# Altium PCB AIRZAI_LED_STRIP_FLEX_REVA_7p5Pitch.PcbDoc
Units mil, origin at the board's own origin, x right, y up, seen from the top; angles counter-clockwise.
Board outline 6727.47 x 711.99 mil, 2 copper layers (Top Layer, Bottom Layer); 43 components, 44 nets, 218 pads, 46 vias.
Unrouted connection lines stored in the file: 63.
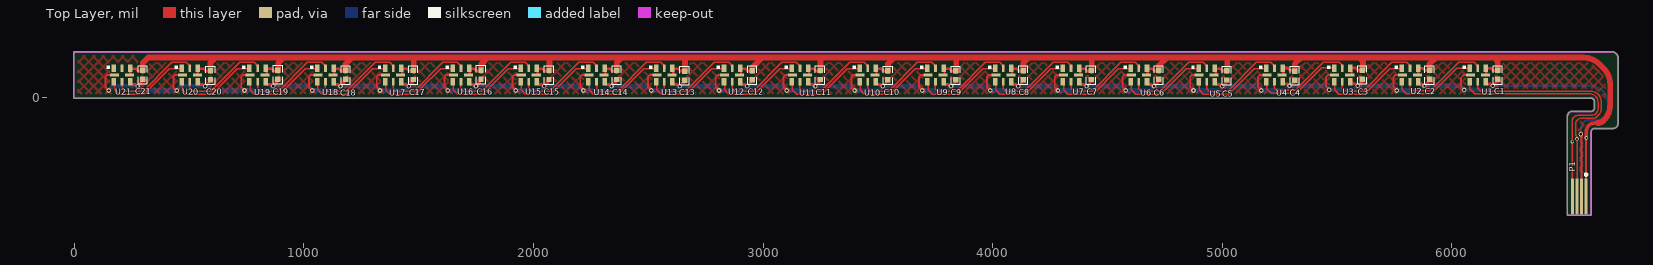
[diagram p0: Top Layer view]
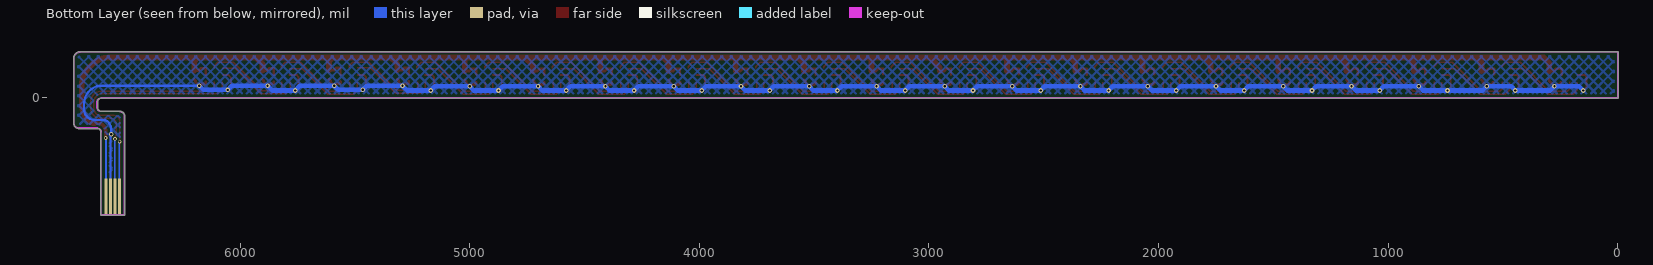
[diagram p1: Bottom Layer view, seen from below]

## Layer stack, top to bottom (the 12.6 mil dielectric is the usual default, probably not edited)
Top Solder: solder mask 0.4, Solder Resist, Dk 3.5
Top Layer: signal copper 1.4
Dielectric 1: dielectric 12.6, FR-4, Dk 4.8
Bottom Layer: signal copper 1.4
Bottom Solder: solder mask 0.4, Solder Resist, Dk 3.5

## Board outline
6503.5,-510.11 ccw(c6506.02,-510.11) 6506.02,-512.63 6604.44,-512.63 ccw(c6604.44,-510.11) 6606.96,-510.11 6606.96,-152 ccw(c6604.44,-152) 6606.95,-151.79 cw(c6622.38,-150.62) 6621.1,-135.2 6702.76,-135.2 ccw(c6702.76,-113) 6724.96,-113 ccw(c6722.44,-113) 6723.97,-111 ccw(c6722.44,-109) 6724.96,-109 6724.96,171.81 ccw(c6697.4,171.81) 6697.4,199.37 0,199.37 ccw(c0,196.85) -2.52,196.85 -2.52,0 ccw(c0,0) 0,-2.52 6604.33,-2.51 ccw(c6604.33,0) 6604.33,-2.51 cw(c6604.33,-19.68) 6621.5,-19.68 6621.5,-43 cw(c6604.33,-43) 6604.33,-60.17 6524.02,-60.17 cw(c6523.67,-80.34) 6524.05,-60.17 6524.02,-60.17 ccw(c6523.67,-80.34) 6503.5,-79.95 ccw(c6506.02,-80) 6503.5,-80
board region "Layer Stack Region 1": 6606.95,-294 6606.96,-510.11 6606.96,-510.61 6606.57,-511.54 6605.87,-512.24 6604.94,-512.63 6604.44,-512.63 6506.02,-512.63 6505.52,-512.63 6504.59,-512.24 6503.88,-511.54 6503.5,-510.61 6503.5,-510.11 6503.5,-294
board region "Layer Stack Region 1": 6368,199.37 6697.4,199.37 6700.12,199.37 6705.44,198.31 6710.45,196.23 6714.97,193.21 6718.8,189.38 6721.82,184.86 6723.9,179.85 6724.96,174.52 6724.96,171.81 6724.96,-109 6724.82,-109.86 6724.57,-110.38 6723.97,-111 6724.57,-111.62 6724.82,-112.14 6724.96,-112.71 6724.96,-117.42 6721.58,-125.58 6715.33,-131.82 6707.17,-135.2 6702.76,-135.2 6621.1,-135.2 6618.13,-135.74 6612.78,-138.48 6608.88,-143.06 6607.01,-148.77 6606.95,-151.79 6606.95,-230 6503.5,-230.01 6503.5,-80 6503.58,-75.95 6506.78,-68.6 6512.55,-63.03 6520.01,-60.1 6524.02,-60.17 6604.33,-60.17 6607.68,-59.84 6613.87,-57.28 6618.61,-52.54 6621.17,-46.35 6621.5,-43 6621.5,-19.69 6621.17,-16.34 6618.61,-10.15 6613.87,-5.41 6607.68,-2.85 6604.33,-2.52 6368,-2.52
board region "Layer Stack Region 1": 6503.5,-294 6503.5,-230.01 6606.95,-230 6606.95,-294
board region "Layer Stack Region 1": 6289,-2.52 0,-2.52 -0.5,-2.52 -1.42,-2.13 -2.13,-1.43 -2.52,-0.5 -2.52,0 -2.52,196.85 -2.52,197.35 -2.13,198.28 -1.42,198.98 -0.5,199.37 0,199.37 6289,199.37
board region "Layer Stack Region 3": 6368,-2.52 6289,-2.52 6289,199.37 6368,199.37

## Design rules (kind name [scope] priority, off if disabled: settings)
Clearance Clearance_polygon_5V [OnLayer('Keep-Out Layer') vs (InNet('+5V') AND InPolygon)] p1: gap=10 ignorepadtopadclearanceinfootprint=FALSE
Clearance Clearance_POLYGON_KEEPOUT [(OnLayer('Keep-Out Layer')) vs (InNet('GND') AND InPolygon)] p2: gap=10 ignorepadtopadclearanceinfootprint=FALSE
Clearance [All] p3: gap=6 ignorepadtopadclearanceinfootprint=FALSE
MinimumSolderMaskSliver [All] p1: minsoldermaskwidth=1
PolygonConnect [All] p1: connectstyle=Direct reliefconductorwidth=10 reliefentries=4 polygonreliefangle="90 Angle" airgapwidth=10
RoomDefinition AIRZAI_LED_STRIP_FLEX_REVA_7p5Pitch [InComponentClass('AIRZAI_LED_STRIP_FLEX_REVA_7p5Pitch')] p1: confinementstyle=ConfineIn formatcopy=TRUE lockcomponents=FALSE outline -3699.89,-5126.44 10960.11,-5126.44 10960.11,4473.56 -3699.89,4473.56
RoutingVias [All] p1: holewidth=28 width=50 viastyle="Through Hole" minholewidth=8 minwidth=16 maxholewidth=28 maxwidth=50
SilkToSilkClearance [All] p1: silktosilkclearance=1
SilkToSolderMaskClearance [IsPad] p1: minsilkscreentomaskgap=2 clearancetoexposedcopper=TRUE
SolderMaskExpansion [All] p1: expansion=4
UnRoutedNet [All] p1: checkbadconnections=TRUE
Width [All] p1: maxlimit=100 minlimit=6 preferedwidth=10
26 further rules are at their usual default settings.

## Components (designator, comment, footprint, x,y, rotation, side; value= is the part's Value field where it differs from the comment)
C1 "0.1µF" 0402CAP 6200.25,98.43 r270 top
C2 "0.1µF" 0402CAP 5903.14,98.43 r270 top
C3 "0.1µF" 0402CAP 5609.7,99.11 r270 top
C4 "0.1µF" 0402CAP 5315.92,95.43 r270 top
C5 "0.1µF" 0402CAP 5020.25,96.11 r270 top
C6 "0.1µF" 0402CAP 4723.87,98.43 r270 top
C7 "0.1µF" 0402CAP 4428.6,98.11 r270 top
C8 "0.1µF" 0402CAP 4133.32,97.46 r270 top
C9 "0.1µF" 0402CAP 3839.05,96.93 r270 top
C10 "0.1µF" 0402CAP 3543.77,97.11 r270 top
C11 "0.1µF" 0402CAP 3248.17,98.11 r270 top
C12 "0.1µF" 0402CAP 2953.22,97.61 r270 top
C13 "0.1µF" 0402CAP 2657.94,95.42 r270 top
C14 "0.1µF" 0402CAP 2362.1,98.11 r270 top
C15 "0.1µF" 0402CAP 2067.39,98.11 r270 top
C16 "0.1µF" 0402CAP 1771.49,99.64 r270 top
C17 "0.1µF" 0402CAP 1476.84,98.11 r270 top
C18 "0.1µF" 0402CAP 1181.57,98.64 r270 top
C19 "0.1µF" 0402CAP 886.73,99.58 r270 top
C20 "0.1µF" 0402CAP 593.02,97.11 r270 top
C21 "0.1µF" 0402CAP 298.06,99.43 r270 top
P1 "Header 4" FFC_4PADS 6555.23,-431.39 r0 top
U1 "APA102-2020-256-8" APA102–2020 6113.25,98.43 r270 top
U2 "APA102-2020-256-8" APA102–2020 5817.98,98.43 r270 top
U3 "APA102-2020-256-8" APA102–2020 5522.7,98.43 r270 top
U4 "APA102-2020-256-8" APA102–2020 5227.43,98.43 r270 top
U5 "APA102-2020-256-8" APA102–2020 4932.25,98.43 r270 top
U6 "APA102-2020-256-8" APA102–2020 4636.87,98.43 r270 top
U7 "APA102-2020-256-8" APA102–2020 4341.6,98.43 r270 top
U8 "APA102-2020-256-8" APA102–2020 4046.32,98.43 r270 top
U9 "APA102-2020-256-8" APA102–2020 3751.05,98.43 r270 top
U10 "APA102-2020-256-8" APA102–2020 3455.77,98.43 r270 top
U11 "APA102-2020-256-8" APA102–2020 3160.5,98.43 r270 top
U12 "APA102-2020-256-8" APA102–2020 2865.22,98.43 r270 top
U13 "APA102-2020-256-8" APA102–2020 2569.94,98.43 r270 top
U14 "APA102-2020-256-8" APA102–2020 2274.67,98.43 r270 top
U15 "APA102-2020-256-8" APA102–2020 1979.39,98.43 r270 top
U16 "APA102-2020-256-8" APA102–2020 1684.12,98.43 r270 top
U17 "APA102-2020-256-8" APA102–2020 1388.84,98.43 r270 top
U18 "APA102-2020-256-8" APA102–2020 1093.57,98.43 r270 top
U19 "APA102-2020-256-8" APA102–2020 798.29,98.43 r270 top
U20 "APA102-2020-256-8" APA102–2020 503.02,98.43 r270 top
U21 "APA102-2020-256-8" APA102–2020 207.74,98.43 r270 top

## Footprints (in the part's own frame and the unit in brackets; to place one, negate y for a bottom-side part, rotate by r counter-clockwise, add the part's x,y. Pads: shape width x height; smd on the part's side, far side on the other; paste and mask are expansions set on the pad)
0402CAP [mm] "Chip Capacitor, Body 1.1x0.5mm, IPC High Density"
  rect 0.6x0.6 smd: 1(-0.5,0) 2(0.5,0)
  silkscreen extent -1.02,-0.51 1.02,0.51, body extent -0.5,-0.3 0.5,0.3, height 0.19
APA102–2020 [mm]
  rect 0.8x0.5 smd: 1(-0.75,0.9) 3(-0.75,-0.9) 4(0.75,-0.9) 6(0.75,0.9)
  rect 0.8x0.3 smd: 2(-0.75,0) 5(0.75,0)
  rect 0.3x1 smd: 7(0,-0.83) 8(0,0.83)
  silkscreen extent -1.02,-1.7 -0.63,-1.32, body extent -1,-1 1,1, height 0.94
FFC_4PADS [mm] "(0.50mm"
  rect 0.3x4 smd: 1(0.75,0) 2(0.25,0) 3(-0.25,0) 4(-0.75,0)
  rect 0.3x4 smd far side: 1(0.75,0) 2(0.25,0) 3(-0.25,0) 4(-0.75,0)
  silkscreen extent 0.64,2.31 0.89,2.56

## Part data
C1 C2 C3 C4 C5 C6 C7 C8 C9 C10 C11 C12 C13 C14 C15 C16 C17 C18 C19 C20 C21: library part C0402-100n, "Capacitor, X7R, ±10%", Case-EIA=0402, Case-Metric=1005, Manufacturer=TDK, Manufacturer Part Number=C1005X7R1C104K, Rated Voltage="16 V", Supplier Part Number 1=445-4952-2-ND, Tolerance=±20%
P1: "Header, 4-Pin"
U1 U2 U3 U4 U5 U6 U7 U8 U9 U10 U11 U12 U13 U14 U15 U16 U17 U18 U19 U20 U21: "DotStar Micro LEDs", Package="SOIC-20 Adafruit Industries"

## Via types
v1: diameter 20, hole 10, Top Layer to Bottom Layer, tented both sides, 43 vias
v2: diameter 16, hole 8, Top Layer to Bottom Layer, tented both sides, 3 vias

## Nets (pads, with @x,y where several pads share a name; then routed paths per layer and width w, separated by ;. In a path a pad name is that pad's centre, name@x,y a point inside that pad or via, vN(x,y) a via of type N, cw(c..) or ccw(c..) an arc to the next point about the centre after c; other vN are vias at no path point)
+5V: C1.1 C2.1 C3.1 C4.1 C5.1 C6.1 C7.1 C8.1 C9.1 C10.1 C11.1 C12.1 C13.1 C14.1 C15.1 C16.1 C17.1 C18.1 C19.1 C20.1 C21.1 P1.1 U1.1 U1.8 U2.1 U2.8 U3.1 U3.8 U4.1 U4.8 U5.1 U5.8 U6.1 U6.8 U7.1 U7.8 U8.1 U8.8 U9.1 U9.8 U10.1 U10.8 U11.1 U11.8 U12.1 U12.8 U13.1 U13.8 U14.1 U14.8 U15.1 U15.8 U16.1 U16.8 U17.1 U17.8 U18.1 U18.8 U19.1 U19.8 U20.1 U20.8 U21.1 U21.8 | length 10913.6
  Top Layer w10: U21.8@242.92,97.69 U21.1@242.92,123.33 ; U20.8@537.92,100 U20.1@537.92,125.64 ; U19.8@837.65,100 U19.1@837.65,125.64 ; U18.8@1131.84,98.42 U18.1@1131.84,125.64 ; U17.8@1428.2,100 U17.1@1428.2,125.64 ; U16.8@1722.3,98.42 U16.1@1722.3,125.64 ; U15.8@2018.75,100 U15.1@2018.75,125.64 ; U14.8@2312.89,98.43 U14.1@2312.89,125.64 ; U13.8@2609.3,100 U13.1@2609.3,125.64 ; U12.8@2903.5,98.43 U12.1@2903.5,125.64 ; U11.8@3199.85,100 U11.1@3199.85,125.64 ; U10.8@3494.05,98.43 U10.1@3494.05,125.64 ; U9.8@3790.4,100 U9.1@3790.4,125.64 ; U8.8@4084.6,98.43 U8.1@4084.6,125.64 ; U7.8@4380.95,100 U7.1@4380.95,125.64 ; U6.8@4675.15,98.43 U6.1@4675.15,125.64 ; U5.8@4971.61,100 U5.1@4971.61,125.64 ; U4.8@5262.95,99.12 5264.8,99.12 5265.7,100.02 U4.1@5265.7,128.64 ; U3.8@5562.06,99.12 5562.96,100.02 U3.1@5562.96,128.64 ; U2.8 5852.5,98.43 5853.41,99.33 U2.1 ; U1.8@6149.61,98.43 6150.52,99.33 U1.1@6150.52,127.95 ; P1.1@6584.76,-399.39 6584.76,-181.5 6584.87,-181.39 6584.87,-177.15 v2(6586.02,-176)
  Top Layer w12: U21.1@247.1,125.65 267.65,125.65 277.49,115.8 C21.1@297.74,115.8 ; U20.1@542.37,125.64 562.92,125.64 572.77,115.8 C20.1@593.01,115.8 ; U19.1@837.65,125.64 858.2,125.64 868.04,115.8 C19.1@888.29,115.8 ; U18.1@1131.84,125.64 1151.49,125.64 1161.33,115.8 C18.1@1181.58,115.8 ; U17.1@1428.2,125.64 1448.75,125.64 1458.59,115.8 C17.1@1478.84,115.8 ; U16.1@1722.3,125.64 1741.95,125.64 1751.79,115.8 C16.1@1772.03,115.8 ; U15.1@2018.75,125.64 2039.3,125.64 2049.14,115.8 C15.1@2069.39,115.8 ; U14.1@2312.89,125.64 2332.54,125.64 2342.38,115.8 C14.1@2362.62,115.8 ; U13.1@2609.3,125.64 2629.85,125.64 2639.69,115.8 C13.1@2659.94,115.8 ; U12.1@2903.5,125.64 2923.14,125.64 2932.99,115.8 C12.1@2953.23,115.8 ; U11.1@3199.85,125.64 3220.4,125.64 3230.25,115.8 C11.1@3250.49,115.8 ; U10.1@3494.05,125.64 3513.7,125.64 3523.54,115.8 C10.1@3543.78,115.8 ; U9.1@3790.4,125.64 3810.95,125.64 3820.8,115.8 C9.1@3841.04,115.8 ; U8.1@4084.6,125.64 4104.25,125.64 4114.09,115.8 C8.1@4134.33,115.8 ; U7.1@4380.95,125.64 4401.51,125.64 4411.35,115.8 C7.1@4431.59,115.8 ; U6.1@4675.15,125.64 4694.8,125.64 4704.64,115.8 C6.1@4724.88,115.8 ; U5.1@4971.61,125.64 4992.16,125.64 5002,115.8 C5.1@5022.25,115.8 ; U4.1@5265.7,128.64 5285.35,128.64 5295.19,118.8 C4.1@5315.43,118.8 ; U3.1@5562.96,128.64 5582.61,128.64 5592.45,118.8 C3.1@5612.69,118.8 ; U2.1 5873.06,127.95 5882.9,118.11 C2.1 ; U1.1@6150.52,127.95 6170.17,127.95 6180.01,118.11 C1.1
  Top Layer w16: v2(6586.02,-176) 6586.02,-146.1 cw(c6620.1,-146.1) 6596,-122 cw(c6622.52,-148.52) 6622.52,-111.01 6635.58,-111.01
  Top Layer w25: C21.1@297.74,115.8 297.74,150 297.81,150 322.02,174.2 617.29,174.2 ; C20.1@593.01,115.8 593.01,150 593.09,150 617.29,174.2 ; C19.1@888.29,115.8 888.29,150 888.36,150 912.56,174.2 ; C18.1@1181.58,115.8 1181.58,144.79 1210.99,174.2 ; 1473.01,174.2 1478.84,168.38 C17.1@1478.84,115.8 ; C16.1@1772.03,115.8 1772.03,145.1 1801.13,174.2 ; 1899.65,174.2 2063.96,174.2 2069.39,168.77 C15.1@2069.39,115.8 ; C14.1@2362.62,115.8 2362.62,152.19 2384.63,174.2 2437.43,174.2 ; 2535.91,174.2 2657.71,174.2 2659.94,171.97 C13.1@2659.94,115.8 ; C12.1@2953.23,115.8 2953.23,129.99 2997.44,174.2 ; 3095.86,174.2 3243.29,174.2 ; C11.1@3250.49,115.8 3250.49,167 3243.29,174.2 ; 3250.49,174.2 3243.29,174.2 ; C10.1@3543.78,115.8 3543.78,146.17 3571.82,174.2 ; C9.1@3841.04,115.8 3841.04,174.2 ; C8.1@4134.33,115.8 4134.33,150.29 4158.24,174.2 ; C7.1@4431.59,115.8 4431.59,168.87 4426.26,174.2 ; C6.1@4724.88,115.8 4724.88,138.99 4760.09,174.2 ; C5.1@5022.25,115.8 5022.25,174.2 ; C4.1@5315.43,118.8 5315.43,145.77 5339.31,169.64 ; 5596.95,174.2 5612.69,158.45 C3.1@5612.69,118.8 ; C2.1 5903.14,146.22 5930.33,173.41 5929.54,174.2 ; C1.1 6200.25,157.76 6183.81,174.2 ; 6635.58,-111.01 ccw(c6635.58,-75.07) 6661,-100.49 ccw(c6590.99,-30.47) 6690,-30.47 6690,56.58 ccw(c6590,56.58) 6660.71,127.29 6643.09,144.91 ccw(c6572.38,74.2) 6572.38,174.2 6183.81,174.2 ; 617.29,174.2 912.56,174.2 ; 912.56,174.2 5022.25,174.2 ; 4426.26,174.2 4344.59,174.2 4426.26,174.2 ; 5022.25,174.2 6183.81,174.2
  Bottom Layer w10: P1.1@6584.76,-399.39 6584.76,-181.5 6584.87,-181.39 6584.87,-177.37 6584.76,-177.26 v2(6586.02,-176)
GND: C1.2 C2.2 C3.2 C4.2 C5.2 C6.2 C7.2 C8.2 C9.2 C10.2 C11.2 C12.2 C13.2 C14.2 C15.2 C16.2 C17.2 C18.2 C19.2 C20.2 C21.2 P1.2 U1.6 U1.7 U2.6 U2.7 U3.6 U3.7 U4.6 U4.7 U5.6 U5.7 U6.6 U6.7 U7.6 U7.7 U8.6 U8.7 U9.6 U9.7 U10.6 U10.7 U11.6 U11.7 U12.6 U12.7 U13.6 U13.7 U14.6 U14.7 U15.6 U15.7 U16.6 U16.7 U17.6 U17.7 U18.6 U18.7 U19.6 U19.7 U20.6 U20.7 U21.6 U21.7 | length 11410.5
  Top Layer w8: v1(150.5,30.69) 136.43,44.76 136.43,90.55 144.31,98.43 U21.7 ; v1(445.78,30.69) 431.7,44.76 431.7,90.55 439.58,98.43 U20.7 ; v1(741.05,30.69) 726.98,44.76 726.98,90.54 734.86,98.43 U19.7 ; v1(1036.32,30.69) 1022.25,44.76 1022.25,90.54 1030.13,98.43 U18.7 ; v1(1331.6,30.69) 1317.53,44.76 1317.53,90.54 1325.41,98.43 U17.7 ; v1(1626.88,30.69) 1612.8,44.76 1612.8,90.54 1620.68,98.43 U16.7 ; v1(1922.15,30.69) 1908.08,44.76 1908.08,90.54 1915.96,98.43 U15.7 ; v1(2217.43,30.69) 2203.35,44.76 2203.35,90.54 2211.24,98.43 U14.7 ; v1(2512.7,30.69) 2498.63,44.76 2498.63,90.54 2506.51,98.43 U13.7 ; v1(2807.98,30.69) 2793.91,44.76 2793.91,90.54 2801.79,98.43 U12.7 ; v1(3103.25,30.69) 3089.18,44.76 3089.18,90.54 3097.06,98.43 U11.7 ; v1(3398.53,30.69) 3384.46,44.76 3384.46,90.54 3392.34,98.43 U10.7 ; v1(3693.8,30.69) 3679.73,44.76 3679.73,90.54 3687.61,98.43 U9.7 ; v1(3989.08,30.69) 3975.01,44.76 3975.01,90.54 3982.89,98.43 U8.7 ; v1(4284.36,30.69) 4270.28,44.76 4270.28,90.54 4278.17,98.43 U7.7 ; v1(4579.63,30.69) 4565.56,44.76 4565.56,90.54 4573.44,98.43 U6.7 ; v1(4875.01,30.69) 4860.94,44.76 4860.94,90.54 4868.82,98.43 U5.7 ; v1(5170.18,30.69) 5156.11,44.76 5156.11,90.54 5163.99,98.43 U4.7 ; v1(5466.46,33.69) 5452.39,47.76 5452.39,89.56 5461.25,98.43 U3.7@5488.02,98.43 ; v1(5760.73,30.69) 5746.66,44.76 5746.66,90.54 5754.54,98.43 U2.7 ; v1(6054.02,33) 6039.94,47.07 6039.94,86.12 6052.25,98.43 U1.7@6076.27,98.43
  Top Layer w10: v1@6563.93,-161.91 v1(6562.02,-160) 6562.02,-170 6565.07,-173.05 P1.2@6565.07,-399.39
  Top Layer w12: U21.6@248,66.59 248,60.68 251.85,56.84 265.02,56.84 273.17,48.69 v1(275.34,48.69) 298.06,71.42 C21.2 ; U20.6@543.28,66.59 543.28,60.68 547.12,56.84 560.3,56.84 568.45,48.69 v1(570.61,48.69) 587.2,65.28 587.2,70.62 C20.2@593.01,76.43 ; U19.6@838.55,66.59 838.55,60.68 842.4,56.84 855.57,56.84 863.72,48.69 v1(865.88,48.69) 882.47,65.28 882.47,70.62 C19.2@888.29,76.43 ; U18.6@1131.84,66.59 1131.84,60.68 1135.69,56.84 1148.86,56.84 1157.01,48.69 v1(1159.17,48.69) 1175.76,65.28 1175.76,70.62 C18.2@1181.58,76.43 ; U17.6@1429.1,66.59 1429.1,60.68 1432.95,56.84 1446.12,56.84 1454.27,48.69 v1(1456.43,48.69) 1473.02,65.28 1473.02,70.62 C17.2@1478.84,76.43 ; U16.6@1722.3,66.59 1722.3,60.68 1726.14,56.84 1739.32,56.84 1747.47,48.69 v1(1749.63,48.69) 1766.22,65.28 1766.22,70.62 C16.2@1772.03,76.43 ; U15.6@2019.65,66.59 2019.65,60.68 2023.5,56.84 2036.67,56.84 2044.82,48.69 v1(2046.99,48.69) 2063.58,65.28 2063.58,70.62 C15.2@2069.39,76.43 ; U14.6@2312.89,66.59 2312.89,60.68 2316.73,56.84 2329.91,56.84 2338.06,48.69 v1(2340.22,48.69) 2356.81,65.28 2356.81,70.62 C14.2@2362.62,76.43 ; U13.6@2610.21,66.59 2610.21,60.68 2614.05,56.84 2627.22,56.84 2635.37,48.69 v1(2637.54,48.69) 2654.13,65.28 2654.13,70.62 C13.2@2659.94,76.43 ; U12.6@2903.5,66.59 2903.5,60.68 2907.34,56.84 2920.51,56.84 2928.66,48.69 v1(2930.83,48.69) 2947.42,65.28 2947.42,70.62 C12.2@2953.23,76.43 ; U11.6@3200.76,66.59 3200.76,60.68 3204.6,56.84 3217.77,56.84 3225.92,48.69 v1(3228.09,48.69) 3244.68,65.28 3244.68,70.62 C11.2@3250.49,76.43 ; U10.6@3494.05,66.59 3494.05,60.68 3497.89,56.84 3511.07,56.84 3519.22,48.69 v1(3521.38,48.69) 3537.97,65.28 3537.97,70.62 C10.2@3543.78,76.43 ; U9.6@3791.31,66.59 3791.31,60.68 3795.15,56.84 3808.32,56.84 3816.47,48.69 v1(3818.64,48.69) 3835.23,65.28 3835.23,70.62 C9.2@3841.04,76.43 ; U8.6@4084.6,66.59 4084.6,60.68 4088.44,56.84 4101.62,56.84 4109.77,48.69 v1(4111.93,48.69) 4128.52,65.28 4128.52,70.62 C8.2@4134.33,76.43 ; U7.6@4381.86,66.59 4381.86,60.68 4385.7,56.84 4398.88,56.84 4407.03,48.69 v1(4409.19,48.69) 4425.78,65.28 4425.78,70.62 C7.2@4431.59,76.43 ; U6.6@4675.15,66.59 4675.15,60.68 4678.99,56.84 4692.17,56.84 4700.32,48.69 v1(4702.48,48.69) 4719.07,65.28 4719.07,70.62 C6.2@4724.88,76.43 ; U5.6@4972.51,66.59 4972.51,60.68 4976.36,56.84 4989.53,56.84 4997.68,48.69 v1(4999.85,48.69) 5016.44,65.28 5016.44,70.62 C5.2@5022.25,76.43 ; U4.6@5265.7,69.59 5265.7,63.68 5269.54,59.84 5282.72,59.84 5290.87,51.69 v1(5293.03,51.69) 5309.62,68.28 5309.62,73.62 C4.2@5315.43,79.43 ; U3.6@5562.96,69.59 5562.96,63.68 5566.8,59.84 5579.98,59.84 5588.13,51.69 v1(5590.29,51.69) 5606.88,68.28 5606.88,73.62 C3.2@5612.69,79.43 ; U2.6 5853.41,62.99 5857.25,59.15 5870.43,59.15 5878.58,51 v1(5880.74,51) 5897.33,67.59 5897.33,72.93 C2.2 ; U1.6@6150.52,68.9 6150.52,62.99 6154.36,59.15 6167.54,59.15 6175.69,51 v1(6177.85,51) 6194.44,67.59 6194.44,72.93 C1.2
  Bottom Layer w10: v1(6177.85,51) 6606.22,51 cw(c6606.22,-18.34) 6655.25,30.69 cw(c6595.47,-29.09) 6680.02,-29.09 6680.02,-51.25 cw(c6633.71,-51.25) 6666.45,-84 cw(c6632.65,-50.2) 6632.65,-98 6596.73,-98 ccw(c6596.73,-128.73) 6575,-107 ccw(c6606.35,-138.35) 6562.02,-138.35 v1(6562.02,-160) cw(c6554.64,-167.37) 6565.07,-167.37 P1.2@6565.07,-399.39
  Bottom Layer w20: v1(150.5,30.69) 168.5,48.69 v1(275.34,48.69) 293.34,30.69 v1(445.78,30.69) 463.78,48.69 v1(570.61,48.69) 588.61,30.69 v1(741.05,30.69) 847.88,30.69 v1(865.88,48.69) 1018.32,48.69 v1(1036.32,30.69) 1141.17,30.69 v1(1159.17,48.69) 1313.6,48.69 v1(1331.6,30.69) 1438.43,30.69 v1(1456.43,48.69) 1608.88,48.69 v1(1626.88,30.69) 1731.63,30.69 v1(1749.63,48.69) 1904.15,48.69 v1(1922.15,30.69) 2028.99,30.69 v1(2046.99,48.69) 2199.43,48.69 v1(2217.43,30.69) 2322.22,30.69 v1(2340.22,48.69) 2494.7,48.69 v1(2512.7,30.69) 2619.54,30.69 v1(2637.54,48.69) 2789.98,48.69 v1(2807.98,30.69) 2912.83,30.69 v1(2930.83,48.69) 3085.25,48.69 v1(3103.25,30.69) 3210.09,30.69 v1(3228.09,48.69) 3380.53,48.69 v1(3398.53,30.69) 3503.38,30.69 v1(3521.38,48.69) 3675.8,48.69 v1(3693.8,30.69) 3800.64,30.69 v1(3818.64,48.69) 3971.08,48.69 v1(3989.08,30.69) 4093.93,30.69 v1(4111.93,48.69) 4266.36,48.69 v1(4284.36,30.69) 4391.19,30.69 v1(4409.19,48.69) 4561.63,48.69 v1(4579.63,30.69) 4684.48,30.69 v1(4702.48,48.69) 4857.01,48.69 v1(4875.01,30.69) 4981.85,30.69 v1(4999.85,48.69) 5152.18,48.69 v1(5170.18,30.69) 5272.03,30.69 v1(5293.03,51.69) 5448.46,51.69 v1(5466.46,33.69) 5572.29,33.69 v1(5590.29,51.69) 5739.73,51.69 v1(5760.73,30.69) 5860.43,30.69 v1(5880.74,51) 6036.02,51 v1(6054.02,33) 6159.85,33 v1(6177.85,51)
LED_CLK_IN: P1.3 U1.5 | length 1282.9
  Top Layer w6: U1.5 6113.25,40.76 6126.02,28 6603.2,28 cw(c6603.2,-19.8) 6637,14 cw(c6603.2,-19.8) 6651,-19.8 6651,-49.44 cw(c6613.44,-49.44) 6640,-76 6635.61,-80.39 cw(c6610,-54.79) 6610,-91 6562.29,-91 ccw(c6562.29,-114.9) 6545.39,-98 ccw(c6560.76,-113.38) 6539.02,-113.38 6539.02,-158.34 ccw(c6552.67,-158.34) 6543.02,-168 cw(c6537.29,-173.72) 6545.39,-173.72 6545.39,-180 v2(6545.27,-180.12) v2(6545.27,-180.12) P1.3@6545.33,-399.33
  Bottom Layer w6: v2(6545.27,-180.12) 6545.39,-180.24 P1.3@6545.39,-399.39
LED_CLK_OUT1: U1.2 U2.5 | length 395.6
  Top Layer w6: U2.5 5817.98,38.15 5826.13,30 5906.74,30 6029.44,152.7 6097.31,152.7 6113.25,136.76 U1.2
LED_CLK_OUT2: U2.2 U3.5 | length 399
  Top Layer w6: U3.5@5522.55,68.9 5522.55,38.68 5533.54,27.69 5614.16,27.69 5739.17,152.7 5802.72,152.7 5820.97,134.45 U2.2@5820.97,127.95
LED_CLK_OUT3: U3.2 U4.5 | length 395.7
  Top Layer w6: U4.5 5227.43,41.68 5238.42,30.69 5319.03,30.69 5441.04,152.7 5510.45,152.7 5525.69,137.45 U3.2@5525.69,128.64
LED_CLK_OUT4: U4.2 U5.5 | length 398.8
  Top Layer w6: U5.5 4932.25,38.68 4943.25,27.69 5023.86,27.69 5148.87,152.7 5212.17,152.7 5230.42,134.45 U4.2@5230.42,127.95
LED_CLK_OUT5: U5.2 U6.5 | length 399
  Top Layer w6: U6.5 4636.87,38.68 4647.87,27.69 4728.48,27.69 4853.49,152.7 4917,152.7 4935.25,134.46 U5.2@4935.25,127.95
LED_CLK_OUT6: U6.2 U7.5 | length 398.9
  Top Layer w6: U7.5 4341.6,38.68 4352.59,27.69 4433.21,27.69 4558.22,152.7 4621.62,152.7 4639.87,134.45 U6.2@4639.87,127.95
LED_CLK_OUT7: U7.2 U8.5 | length 398.9
  Top Layer w6: U8.5 4046.32,38.68 4057.32,27.69 4137.93,27.69 4262.94,152.7 4326.35,152.7 4344.59,134.45 U7.2@4344.59,127.95
LED_CLK_OUT8: U8.2 U9.5 | length 398.9
  Top Layer w6: U9.5 3751.05,38.68 3762.04,27.69 3842.65,27.69 3967.67,152.7 4031.07,152.7 4049.32,134.45 U8.2@4049.32,127.95
LED_CLK_OUT9: U9.2 U10.5 | length 398.9
  Top Layer w6: U10.5 3455.77,38.68 3466.77,27.69 3547.38,27.69 3672.39,152.7 3735.79,152.7 3754.04,134.45 U9.2@3754.04,127.95
LED_CLK_OUT10: U10.2 U11.5 | length 398.9
  Top Layer w6: U11.5 3160.5,38.68 3171.49,27.69 3252.1,27.69 3377.12,152.7 3440.52,152.7 3458.77,134.45 U10.2@3458.77,127.95
LED_CLK_OUT11: U11.2 U12.5 | length 398.9
  Top Layer w6: U12.5 2865.22,38.68 2876.21,27.69 2956.83,27.69 3081.84,152.7 3145.24,152.7 3163.49,134.45 U11.2@3163.49,127.95
LED_CLK_OUT12: U12.2 U13.5 | length 398.9
  Top Layer w6: U13.5 2569.94,38.68 2580.94,27.69 2661.55,27.69 2786.56,152.7 2849.97,152.7 2868.21,134.45 U12.2@2868.21,127.95
LED_CLK_OUT13: U13.2 U14.5 | length 398.9
  Top Layer w6: U14.5@2274.61,68.9 2274.61,38.68 2285.61,27.69 2366.22,27.69 2491.23,152.7 2554.69,152.7 2572.94,134.45 U13.2@2572.94,127.95
LED_CLK_OUT14: U14.2 U15.5 | length 398.7
  Top Layer w6: U15.5@1979.54,68.9 1979.54,38.69 1990.54,27.69 2071.15,27.69 2196.16,152.7 2259.42,152.7 2277.66,134.45 U14.2@2277.66,127.95
LED_CLK_OUT15: U15.2 U16.5 | length 399
  Top Layer w6: U16.5@1684.02,68.9 1684.02,38.68 1695.02,27.69 1775.63,27.69 1900.64,152.7 1964.14,152.7 1982.39,134.45 U15.2@1982.39,127.95
LED_CLK_OUT16: U16.2 U17.5 | length 398.9
  Top Layer w6: U17.5 1388.84,38.69 1399.84,27.69 1480.45,27.69 1605.46,152.7 1668.86,152.7 1687.11,134.45 U16.2@1687.11,127.95
LED_CLK_OUT17: U17.2 U18.5 | length 398.9
  Top Layer w6: U18.5 1093.57,38.68 1104.56,27.69 1185.17,27.69 1310.19,152.7 1373.59,152.7 1391.84,134.45 U17.2@1391.84,127.95
LED_CLK_OUT18: U18.2 U19.5 | length 398.9
  Top Layer w6: U19.5 798.29,38.69 809.29,27.69 889.9,27.69 1014.91,152.7 1078.31,152.7 1096.56,134.45 U18.2@1096.56,127.95
LED_CLK_OUT19: U19.2 U20.5 | length 392.4
  Top Layer w6: U20.5 503.02,38.69 514.01,27.69 594.63,27.69 719.64,152.7 783.04,152.7 U19.2@801.29,134.46
LED_CLK_OUT20: U20.2 U21.5 | length 392.4
  Top Layer w6: U21.5 207.74,38.69 218.74,27.69 299.35,27.69 424.36,152.7 487.76,152.7 U20.2@506.01,134.46
LED_SDI: P1.4 U1.4 | length 1295
  Top Layer w6: U1.4 6077.82,37.2 6099.02,16 6602,16 cw(c6602,-17.8) 6625.9,6.1 6626,6 cw(c6599.44,-20.56) 6637,-20.56 6637,-48.69 cw(c6609.69,-48.69) 6629.01,-67.99 6627.07,-69.93 cw(c6610,-52.86) 6610,-77 6552.73,-77 ccw(c6552.73,-107.73) 6531,-86 ccw(c6545.49,-100.49) 6525,-100.49 v2(6525,-192) ; P1.4@6525.7,-399.39 v2@6525.7,-193.02
  Bottom Layer w6: v2(6525,-192) 6526.02,-193.02 P1.4@6526.02,-399.07
LED_SDO_1: U1.3 U2.4 | length 382.5
  Top Layer w6: U2.4 5782.54,35.2 5800.74,17 5910.74,17 6021.69,127.95 U1.3
LED_SDO_2: U2.3 U3.4 | length 382.8
  Top Layer w6: U3.4@5489.96,66.59 5489.96,32.89 5508.16,14.69 5618.16,14.69 5729.11,125.64 U2.3@5785.54,125.64
LED_SDO_3: U3.3 U4.4 | length 382.6
  Top Layer w6: U4.4@5194.84,69.59 5194.84,35.89 5213.03,17.69 5323.03,17.69 5433.99,128.64 U3.3@5490.26,128.64
LED_SDO_4: U4.3 U5.4 | length 382.5
  Top Layer w6: U5.4@4899.66,66.59 4899.66,32.89 4917.86,14.69 5027.86,14.69 5138.81,125.64 U4.3@5194.99,125.64
LED_SDO_5: U5.3 U6.4 | length 382.7
  Top Layer w6: U6.4@4604.28,66.59 4604.28,32.89 4622.48,14.69 4732.48,14.69 4843.44,125.64 U5.3@4899.81,125.64
LED_SDO_6: U6.3 U7.4 | length 382.6
  Top Layer w6: U7.4@4309.01,66.59 4309.01,32.89 4327.21,14.69 4437.21,14.69 4548.16,125.64 U6.3@4604.43,125.64
LED_SDO_7: U7.3 U8.4 | length 382.6
  Top Layer w6: U8.4@4013.73,66.59 4013.73,32.89 4031.93,14.69 4141.93,14.69 4252.88,125.64 U7.3@4309.16,125.64
LED_SDO_8: U8.3 U9.4 | length 382.6
  Top Layer w6: U9.4@3718.46,66.59 3718.46,32.89 3736.65,14.69 3846.65,14.69 3957.61,125.64 U8.3@4013.88,125.64
LED_SDO_9: U9.3 U10.4 | length 382.6
  Top Layer w6: U10.4@3423.18,66.59 3423.18,32.89 3441.38,14.69 3551.38,14.69 3662.33,125.64 U9.3@3718.61,125.64
LED_SDO_10: U10.3 U11.4 | length 382.6
  Top Layer w6: U11.4@3127.91,66.59 3127.91,32.89 3146.1,14.69 3256.1,14.69 3367.06,125.64 U10.3@3423.33,125.64
LED_SDO_11: U11.3 U12.4 | length 382.6
  Top Layer w6: U12.4@2832.63,66.59 2832.63,32.89 2850.83,14.69 2960.83,14.69 3071.78,125.64 U11.3@3128.06,125.64
LED_SDO_12: U12.3 U13.4 | length 382.6
  Top Layer w6: U13.4@2537.36,66.59 2537.36,32.89 2555.55,14.69 2665.55,14.69 2776.51,125.64 U12.3@2832.78,125.64
LED_SDO_13: U13.3 U14.4 | length 382.7
  Top Layer w6: U14.4@2242.03,66.59 2242.03,32.89 2260.22,14.69 2370.22,14.69 2481.17,125.64 U13.3@2537.51,125.64
LED_SDO_14: U14.3 U15.4 | length 382.5
  Top Layer w6: U15.4@1946.95,66.59 1946.95,32.89 1965.15,14.69 2075.15,14.69 2186.1,125.64 U14.3@2242.23,125.64
LED_SDO_15: U15.3 U16.4 | length 382.7
  Top Layer w6: U16.4@1651.43,66.59 1651.43,32.89 1669.63,14.69 1779.63,14.69 1890.58,125.64 U15.3@1946.95,125.64
LED_SDO_16: U16.3 U17.4 | length 392.7
  Top Layer w6: U17.4@1356.25,66.59 1356.25,32.89 1374.45,14.69 1484.45,14.69 1514.86,45.1 ; 1507.7,37.97 1595.37,125.64 U16.3@1651.68,125.64
LED_SDO_17: U17.3 U18.4 | length 382.6
  Top Layer w6: U18.4@1060.98,66.59 1060.98,32.89 1079.17,14.69 1189.17,14.69 1300.13,125.64 U17.3@1356.4,125.64
LED_SDO_18: U18.3 U19.4 | length 382.6
  Top Layer w6: U19.4@765.7,66.59 765.7,32.89 783.9,14.69 893.9,14.69 1004.85,125.64 U18.3@1061.13,125.64
LED_SDO_19: U19.3 U20.4 | length 382.6
  Top Layer w6: U20.4@470.43,66.59 470.43,32.89 488.63,14.69 598.63,14.69 709.58,125.64 U19.3@765.85,125.64
LED_SDO_20: U20.3 U21.4 | length 382.6
  Top Layer w6: U21.4@175.16,66.59 175.16,32.89 193.35,14.69 303.35,14.69 414.3,125.64 U20.3@470.58,125.64
pads on no net: U21.2 U21.3

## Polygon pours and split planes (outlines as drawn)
GND on Bottom Layer "gnd_top" (hatched 45Degree grid 30 track 9.49, remove dead copper, pour order 5): 6503.5,-478.11 ccw(c6506.02,-478.11) 6506.02,-480.63 6604.44,-480.63 ccw(c6604.44,-478.11) 6606.96,-478.11 6606.96,-152 ccw(c6604.44,-152) 6606.95,-151.79 cw(c6622.38,-150.62) 6621.1,-135.2 6702.76,-135.2 ccw(c6702.76,-113) 6724.96,-113 ccw(c6722.44,-113) 6723.97,-111 ccw(c6722.44,-109) 6724.96,-109 6724.96,171.81 ccw(c6697.4,171.81) 6697.4,199.37 0,199.37 ccw(c0,196.85) -2.52,196.85 -2.52,0 ccw(c0,0) 0,-2.52 6604.33,-2.51 ccw(c6604.33,0) 6604.33,-2.51 cw(c6604.33,-19.68) 6621.5,-19.68 6621.5,-43 cw(c6604.33,-43) 6604.33,-60.17 6524.02,-60.17 cw(c6523.67,-80.34) 6524.05,-60.17 6524.02,-60.17 ccw(c6523.67,-80.34) 6503.5,-79.95 ccw(c6506.02,-80) 6503.5,-80
GND on Top Layer "gnd_top" (hatched 45Degree grid 30 track 9.49, remove dead copper, pour order 1): 6503.5,-478.11 ccw(c6506.02,-478.11) 6506.02,-480.63 6604.44,-480.63 ccw(c6604.44,-478.11) 6606.96,-478.11 6606.96,-152 cw(c6622.49,-150.72) 6621.1,-135.2 6702.76,-135.2 ccw(c6702.76,-113) 6724.96,-113 ccw(c6722.44,-113) 6723.97,-111 ccw(c6722.44,-109) 6724.96,-109 6724.96,171.81 ccw(c6697.4,171.81) 6697.4,199.37 0,199.37 ccw(c0,196.85) -2.52,196.85 -2.52,0 ccw(c0,0) 0,-2.52 6604.33,-2.51 cw(c6604.33,-19.68) 6621.5,-19.68 6621.5,-43 cw(c6604.33,-43) 6604.33,-60.17 6524.02,-60.17 ccw(c6523.66,-80.33) 6503.5,-79.95

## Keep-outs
Keep-Out Layer:
  lines w5: 6722.44,-113 cw(c6702.76,-113) 6702.76,-132.68 6621,-132.68 ccw(c6622.38,-150.62) 6604.44,-152 6604.44,-510.11 6506.02,-510.11 6506.02,-80 cw(c6523.67,-80.33) 6524,-62.69 6604.33,-62.68 ccw(c6604.33,-43) 6624.02,-43 6624.02,-19.68 ccw(c6604.33,-19.68) 6604.33,0 ; 6722.44,-109 6722.44,171.81 ccw(c6697.4,171.81) 6697.4,196.85 6624.02,196.85 6289.37,196.85 0,196.85 0,0 6604.33,0 ; 6604.33,0 6604.33,0

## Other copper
Top Layer:
  pour cut-out: 6504.24,-511.89 6606.22,-511.89 6606.22,-336.22 6606,-336 6504.24,-336
  pour cut-out: 150.36,152.7 150.65,153 275.65,153 275.65,39 275.34,38.68 150.65,38.68 150.65,152.4
  pour cut-out: 445.62,152.7 445.91,153 570.91,153 570.91,39 570.6,38.68 445.91,38.68 445.91,152.4
  pour cut-out: 1331.31,152.7 1331.61,153 1456.61,153 1456.61,39 1456.29,38.68 1331.61,38.68 1331.61,152.4
  pour cut-out: 1035.88,152.7 1036.18,153 1161.18,153 1161.18,39 1160.86,38.68 1036.18,38.68 1036.18,152.4
  pour cut-out: 740.91,152.7 741.21,153 866.21,153 866.21,39 865.89,38.68 741.21,38.68 741.21,152.4
  pour cut-out: 2512.41,152.7 2512.71,153 2637.71,153 2637.71,39 2637.39,38.68 2512.71,38.68 2512.71,152.4
  pour cut-out: 2216.93,152.7 2217.23,153 2342.23,153 2342.23,39 2341.91,38.68 2217.23,38.68 2217.23,152.4
  pour cut-out: 1626.58,152.7 1626.88,153 1751.88,153 1751.88,39 1751.57,38.68 1626.88,38.68 1626.88,152.4
  pour cut-out: 1922.1,152.7 1922.4,153 2047.4,153 2047.4,39 2047.09,38.69 1922.4,38.69 1922.4,152.4
  pour cut-out: 3693.51,152.7 3693.81,153 3818.81,153 3818.81,39 3818.49,38.68 3693.81,38.68 3693.81,152.4
  pour cut-out: 3398.09,152.7 3398.39,153 3523.39,153 3523.39,39 3523.07,38.68 3398.39,38.68 3398.39,152.4
  pour cut-out: 2807.69,152.7 2807.98,153 2932.98,153 2932.98,39 2932.67,38.68 2807.98,38.68 2807.98,152.4
  pour cut-out: 3103.11,152.7 3103.41,153 3228.41,153 3228.41,39 3228.09,38.68 3103.41,38.68 3103.41,152.4
  pour cut-out: 4874.72,152.7 4875.02,153 5000.02,153 5000.02,39 4999.7,38.68 4875.02,38.68 4875.02,152.4
  pour cut-out: 4579.19,152.7 4579.49,153 4704.49,153 4704.49,39 4704.17,38.68 4579.49,38.68 4579.49,152.4
  pour cut-out: 3988.79,152.7 3989.09,153 4114.09,153 4114.09,39 4113.77,38.68 3989.09,38.68 3989.09,152.4
  pour cut-out: 4284.21,152.7 4284.51,153 4409.51,153 4409.51,39 4409.2,38.68 4284.51,38.68 4284.51,152.4
  pour cut-out: 5465.32,152.7 5465.61,153 5590.61,153 5590.61,39 5590.3,38.68 5465.61,38.68 5465.61,152.4
  pour cut-out: 5169.89,152.7 5170.19,153 5295.19,153 5295.19,39 5294.87,38.68 5170.19,38.68 5170.19,152.4
  pour cut-out: 5760.44,152.7 5760.74,153 5885.74,153 5885.74,39 5885.42,38.68 5760.74,38.68 5760.74,152.4
  pour cut-out: 6055.72,152.7 6056.02,153 6181.02,153 6181.02,39 6180.7,38.68 6056.02,38.68 6056.02,152.4
Bottom Layer:
  pour cut-out: 6504.24,-511.89 6606.22,-511.89 6606.22,-336.22 6606,-336 6504.24,-336

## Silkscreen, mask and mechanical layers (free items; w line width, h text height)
Mechanical 1:
  lines w5: 139,98.43 6289.37,98.43 6289.37,196.85 ; 207.74,88.93 207.74,107.93 ; 485.25,98 cw(c485.68,98) 485.68,98.43 ; 503.02,88.93 503.02,107.93 ; 6461.31,-242.91 6722.44,-242.91 ; 6461.31,-62.99 6722.44,-62.99 ; 798.29,88.93 798.29,107.93 ; 798.29,88.93 798.29,107.93 ; 798.29,88.93 798.29,107.93 ; 798.29,88.93 798.29,107.93 ; 1093.57,88.93 1093.57,107.93 ; 1093.57,88.93 1093.57,107.93 ; 1093.57,88.93 1093.57,107.93 ; 1093.57,88.93 1093.57,107.93 ; 1388.84,88.93 1388.84,107.93 ; 1388.84,88.93 1388.84,107.93 ; 1388.84,88.93 1388.84,107.93 ; 1388.84,88.93 1388.84,107.93 ; 1684.12,88.93 1684.12,107.93 ; 1684.12,88.93 1684.12,107.93 ; 1684.12,88.93 1684.12,107.93 ; 1684.12,88.93 1684.12,107.93 ; 1979.39,88.93 1979.39,107.93 ; 1979.39,88.93 1979.39,107.93 ; 1979.39,88.93 1979.39,107.93 ; 1979.39,88.93 1979.39,107.93 ; 2274.67,88.93 2274.67,107.93 ; 2274.67,88.93 2274.67,107.93 ; 2274.67,88.93 2274.67,107.93 ; 2274.67,88.93 2274.67,107.93 ; 2569.94,88.93 2569.94,107.93 ; 2569.94,88.93 2569.94,107.93 ; 2569.94,88.93 2569.94,107.93 ; 2569.94,88.93 2569.94,107.93 ; 2865.22,88.93 2865.22,107.93 ; 2865.22,88.93 2865.22,107.93 ; 2865.22,88.93 2865.22,107.93 ; 2865.22,88.93 2865.22,107.93 ; 3160.5,88.93 3160.5,107.93 ; 3160.5,88.93 3160.5,107.93 ; 3160.5,88.93 3160.5,107.93 ; 3160.5,88.93 3160.5,107.93 ; 3455.77,88.93 3455.77,107.93 ; 3455.77,88.93 3455.77,107.93 ; 3455.77,88.93 3455.77,107.93 ; 3455.77,88.93 3455.77,107.93 ; 3751.05,88.93 3751.05,107.93 ; 3751.05,88.93 3751.05,107.93 ; 3751.05,88.93 3751.05,107.93 ; 3751.05,88.93 3751.05,107.93 ; 4046.32,88.93 4046.32,107.93 ; 4046.32,88.93 4046.32,107.93 ; 4046.32,88.93 4046.32,107.93 ; 4046.32,88.93 4046.32,107.93 ; 4341.6,88.93 4341.6,107.93 ; 4341.6,88.93 4341.6,107.93 ; 4341.6,88.93 4341.6,107.93 ; 4341.6,88.93 4341.6,107.93 ; 4636.87,88.93 4636.87,107.93 ; 4636.87,88.93 4636.87,107.93 ; 4636.87,88.93 4636.87,107.93 ; 4636.87,88.93 4636.87,107.93 ; 4932.15,88.93 4932.15,107.93 ; 4932.15,88.93 4932.15,107.93 ; 4932.15,88.93 4932.15,107.93 ; 4932.15,88.93 4932.15,107.93 ; 5227.43,88.93 5227.43,107.93 ; 5227.43,88.93 5227.43,107.93 ; 5227.43,88.93 5227.43,107.93 ; 5227.43,88.93 5227.43,107.93 ; 5522.7,88.93 5522.7,107.93 ; 5522.7,88.93 5522.7,107.93 ; 5522.7,88.93 5522.7,107.93 ; 5522.7,88.93 5522.7,107.93 ; 5817.98,88.93 5817.98,107.93 ; 5817.98,88.93 5817.98,107.93 ; 5817.98,88.93 5817.98,107.93 ; 5817.98,88.93 5817.98,107.93 ; 6113.25,88.93 6113.25,107.93 ; 6113.25,88.93 6113.25,107.93 ; 6113.25,88.93 6113.25,107.93 ; 6113.25,88.93 6113.25,107.93 ; 6113.25,88.93 6113.25,107.93 ; 6113.25,88.93 6113.25,107.93 ; 6113.25,88.93 6113.25,107.93 ; 6113.25,88.93 6113.25,107.93
  text "Base PCB" at 6209,-251 h30
Mechanical 2:
  rectangle: 6506.02,-510 6604.44,-351
  lines w5: 6368,-415 6493,-415 ; 6472,-428 6493,-415 ; 6472,-402 6493,-415
  text "Stiffener Location" at 5850.65,-426 h30
Mechanical 4:
  lines w5: 6722.44,-113 cw(c6702.76,-113) 6702.76,-132.69 6621,-132.69 ccw(c6622.38,-150.62) 6604.44,-152 6604.44,-510.11 6506.02,-510.11 6506.02,-80 cw(c6523.67,-80.34) 6524,-62.69 6604.33,-62.69 ccw(c6604.33,-43) 6624.02,-43 6624.02,-19.68 ccw(c6604.33,-19.68) 6604.33,0 ; 6722.44,-109 6722.44,171.81 ccw(c6697.4,171.81) 6697.4,196.85 6624.02,196.85 6289.37,196.85 0,196.85 0,0 6604.33,0 ; 6604.33,0 6604.33,0
Drill Drawing:
  text "PWB, LED STRIP FLEX" at 7741.33,-5537.09 h157.48
  text "PWB-020218-001" at 7928.33,-5862.87 h127.95
  text "1" at 10353.53,-5921.93 h78.74
  text "1" at 10164.55,-5925.87 h78.74
Mechanical 17:
  text "NOTES: /  / 1. ALL ASSEMBLY MATERIALS TO BE RoHS COMPLIANT. /  / 2. MATERIAL: /           • FLEXIBLE METAL CLAD DIELECTRIC IAW                 /             IPC-4204/11 E1E2 O0/0 CU W7 T/T /           • STIFFENER IAW IPC-4203/1-E1E8M1 /  / 3. FINISH:  IMMERSION GOLD /  / ALL EXPOSED CONDUCTIVE PATTERN AREAS NOT COVERED WITH COVERLAY MATERIAL OR OTHER PLATING  / SHALL BE IMMERSION GOLD (0.000030-0.000090 mm) OVER ELECTROLESS NICKEL (0.001-0.006 mm). /  / 4. LEGEND SHALL BE WHITE, PERMANENT, ORGANIC, NON-CONDUCTIVE UV OR EPOXY TYPE INK APPLIED  / TO THE TOP SIDE OF THE BOARD. THERE SHALL BE NO LEGEND ON ANY SOLDERABLE COMPONENT LAND. /  / 5. ALL ASSEMBLY MATERIALS TO BE RoHS COMPLIANT. /  / 6. ANY LABELS OR COMPOSITION OF, APPLIED TO THE BOARD NEED TO BE APPROVIED BY AIRZAI /  / 7. MINIMUM TRACE WIDTHS: /           EXTERNAL: 0.152 mm  INTERNAL: N/A /  / 8. MINIMUM SPACE BETWEEN FEATURES: /          EXTERNAL: 0.15 mm  INTERNAL: N/A /  / 9. Overall Board Thickness: 0.1mm" at -20,-4431.85 h78.74
  text "PWB, LED STRIP FLEX" at 7783.95,-5611.68 h157.48
  text "PWA-020218-001" at 7977.95,-5902.68 h127.95
  text "1" at 10156.68,-5914.06 h59.06
  text "1" at 10345.66,-5914.06 h59.06
Mechanical 18:
  lines w5: -3951,-3780 -3751,-3780 ; -3951,-1405 -3751,-1405 ; -3951,970 -3751,970 ; -1451,-6155 -1451,-5955 ; -1451,3145 -1451,3345 ; 1049,-6155 1049,-5955 ; 1049,3145 1049,3345 ; 3549,-6155 3549,-5955 ; 3549,3145 3549,3345 ; 6049,-6155 6049,-5955 ; 6049,3145 6049,3345 ; 6348.2,-5657.21 10848.2,-5657.21 ; 6348.2,-5415.48 7418.87,-5415.48 ; 6348.2,-5181.43 7418.87,-5181.43 ; 6348.2,-4970.6 7418.87,-4970.6 ; 6349,-5955 10849,-5955 ; 6973.99,-5958.2 6973.99,-4758.2 ; 7418.87,-5957.21 7418.87,-4757.21 ; 7418.87,-5290.28 10848.06,-5290.28 ; 7758.83,-4757.21 10848.2,-4757.21 ; 7848.2,-4757.21 6348.2,-4757.21 ; 8549,-6155 8549,-5955 ; 8549,3145 8549,3345 ; 10471.83,-5957.21 10471.83,-5657.21 ; 10849,-4755 10849,-5955 ; 10849,-3780 11049,-3780 ; 10849,970 11049,970 ; 4948.2,-5957.21 4948.2,-4757.21 6348.2,-4757.21 ; 4948.2,-5957.21 6348.2,-5957.21 ; 4948.2,-5957.21 6348.2,-5957.21 ; 6348.2,-5957.21 6348.2,-4757.21 ; 6348.2,-5957.21 10848.2,-5957.21 ; 6348.2,-5957.21 10848.2,-5957.21 ; 10848.2,-5957.21 10848.2,-4757.21 ; 10848.2,-5957.21 10848.2,-4757.21 ; 10849,-5955 -3751,-5955 -3751,3145 10849,3145 10849,-5955 ; -3951,-6155 11049,-6155 11049,3345 -3951,3345 -3951,-6155
  text "1" at -2719.66,3215 h70
  text "2" at -224,3215 h70
  text "3" at 2265.34,3215 h70
  text "4" at 4772.01,3215 h70
  text "5" at 7271,3215 h70
  text "6" at 9776,3215 h70
  text "A" at -3876,2072 h70
  text "A" at 10924,2072 h70
  text "B" at -3876,-308 h70
  text "B" at 10924,-308 h70
  text "C" at -3876,-2683 h70
  text "C" at 10924,-2683 h70
  text "AIRZAI PROPRIETARY & CONFIDENTIAL" at 6504.12,-4646.34 h127.95
  text "DATE:" at 7004.5,-4819.42 h45
  text "ENGINEER:" at 6370.65,-4825.72 h45
  text "UNLESS OTHERWISE SPECIFIED" at 5047.81,-4886.35 h59.06
  text "02/05/19" at 7011.83,-4928.03 h59.06
  text "FD" at 6563.52,-4934.3 h78.74
  text "DIMENSIONS ARE IN MM" at 5169.86,-5012.33 h59.06
  text "PCB DESIGNER:" at 6366.71,-5034.1 h45
  text "DATE:" at 6992.69,-5035.95 h45
  text "D" at -3876,-5053 h70
  text "D" at 10924,-5053 h70
  text "AIRZAI" at 7709.83,-5091.22 h127.95
  text "TOLERANCES" at 5370.65,-5138.31 h59.06
  text "02/05/19" at 7011.83,-5142.6 h59.06
  text "DFM" at 6537.14,-5144.18 h78.74
  text "DATE:" at 6992.69,-5248.55 h45
  text "CHECK" at 6366.71,-5250.64 h45
  text "ANGULAR" at 5854.9,-5295.8 h59.06
  text "DECIMALS" at 5051.75,-5307.61 h59.06
  text "TITLE:" at 7470.66,-5354.02 h45
  text "FD" at 6602.89,-5367.37 h78.74
  text ".XX +/- .127MM" at 5004.5,-5465.09 h59.06
  text "+/-" at 5843.09,-5469.02 h59.06
  text "REL" at 6378.52,-5481.62 h45
  text "DATE:" at 7008.44,-5488.71 h45
  text "FD" at 6593.05,-5583.91 h78.74
  text ".XXX +/- .080MM" at 4992.69,-5626.5 h59.06
  text "SCALE:" at 7013.95,-5721.78 h45
  text "REV:" at 10494.27,-5720.99 h45
  text "DWG NO:" at 7465.13,-5729.65 h45
  text "SIZE" at 6378.52,-5732.8 h45
  text "B" at 6582.26,-5863.39 h120
  text "DO NOT SCALE DRAWING" at 5047.81,-5866.66 h70.87
  text "A" at 10577.94,-5882.56 h120
  text "1:1" at 7062.57,-5887.02 h120
  text "SHEET" at 9929.7,-5918.63 h45
  text "OF" at 10193.48,-5918.63 h45
  text "1" at -2719.66,-6085 h70
  text "2" at -224,-6085 h70
  text "3" at 2265.34,-6085 h70
  text "4" at 4772.01,-6085 h70
  text "5" at 7271,-6085 h70
  text "6" at 9776,-6085 h70

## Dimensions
0,196.85 to 6289.37,196.85 on Mechanical 5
